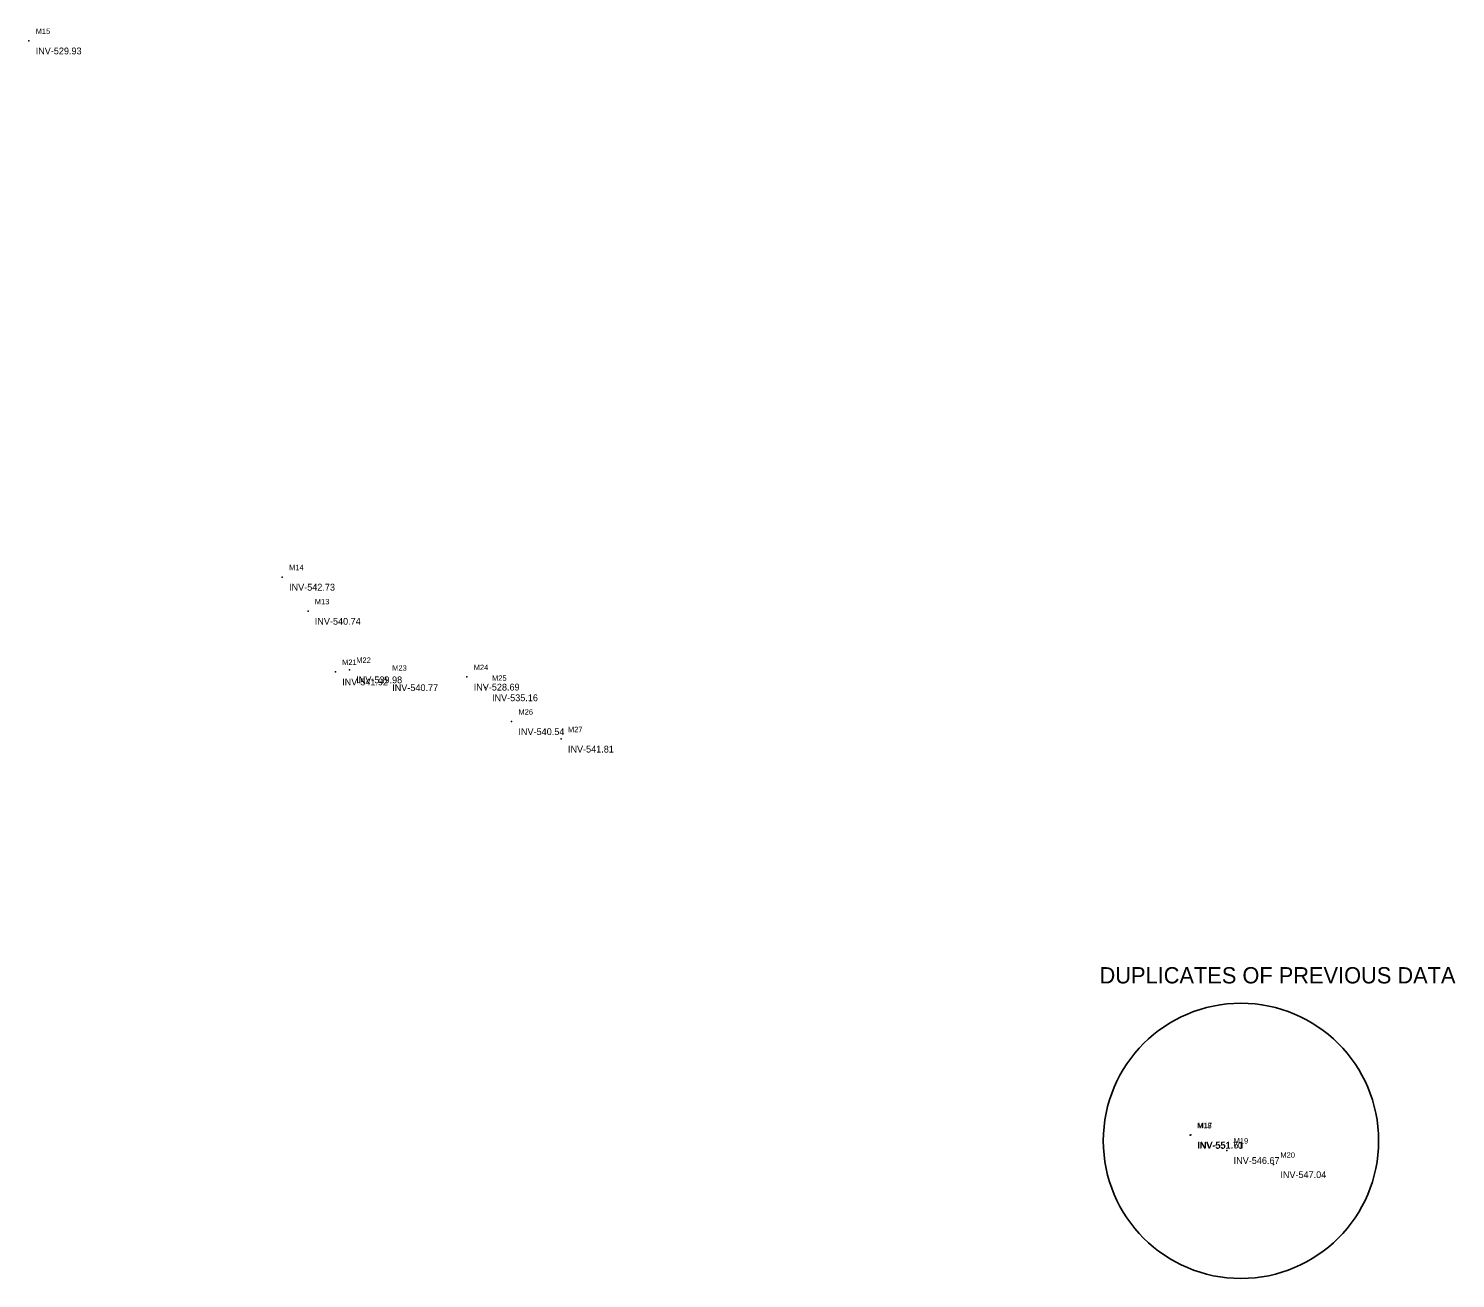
# Model space of a CAD drawing. Extents: x 1728037 to 1741597, y 649934 to 653706.
# Drawn here: x 1728037 to 1729088, y 652785 to 653706 of the extents above; entities that cross this region are included whole.
import ezdxf

# ---------------------------------------------------------------- set-up
doc = ezdxf.new("R2010")
doc.units = 0
for name, color, linetype in [('SURVEY - CENTERLINE - Preliminary', 7, 'Continuous'), ('SURVEY - DRAINAGE - Storm Sewer - Points - Elevations', 7, 'Continuous'), ('SURVEY - DRAINAGE - Storm Sewer - Points - Locators', 7, 'Continuous'), ('SURVEY - DRAINAGE - Storm Sewer - Points - Numbers', 7, 'Continuous')]:
    doc.layers.add(name, color=color, linetype=linetype)

msp = doc.modelspace()

# ---------------------------------------------------------------- linework, layer by layer
at = {"layer": 'SURVEY - CENTERLINE - Preliminary'}
msp.add_circle((1728930, 652886.74), 101.36, dxfattribs=at)
at = {"layer": 'SURVEY - DRAINAGE - Storm Sewer - Points - Locators'}
for p, q in [((1728037.62, 653696.98), (1728037.12, 653696.98)), ((1728037.37, 653696.73), (1728037.37, 653697.23)), ((1728037.37, 653696.98), (1728037.37, 653696.98)), ((1728037.37, 653696.98), (1728037.37, 653696.98)), ((1728224.23, 653302), (1728223.73, 653302)), ((1728223.98, 653301.75), (1728223.98, 653302.25)), ((1728223.98, 653302), (1728223.98, 653302)), ((1728223.98, 653302), (1728223.98, 653302)), ((1728243.19, 653276.88), (1728242.69, 653276.88)), ((1728242.94, 653276.63), (1728242.94, 653277.13)), ((1728242.94, 653276.88), (1728242.94, 653276.88)), ((1728242.94, 653276.88), (1728242.94, 653276.88)), ((1728263.33, 653232.23), (1728262.83, 653232.23)), ((1728263.08, 653231.98), (1728263.08, 653232.48)), ((1728263.08, 653232.23), (1728263.08, 653232.23)), ((1728263.08, 653232.23), (1728263.08, 653232.23)), ((1728273.69, 653233.76), (1728273.19, 653233.76)), ((1728273.44, 653233.51), (1728273.44, 653234.01)), ((1728273.44, 653233.76), (1728273.44, 653233.76)), ((1728273.44, 653233.76), (1728273.44, 653233.76)), ((1728300.18, 653228.01), (1728299.68, 653228.01)), ((1728299.93, 653227.76), (1728299.93, 653228.26)), ((1728299.93, 653228.01), (1728299.93, 653228.01)), ((1728299.93, 653228.01), (1728299.93, 653228.01)), ((1728360.19, 653228.41), (1728359.69, 653228.41)), ((1728359.94, 653228.16), (1728359.94, 653228.66)), ((1728359.94, 653228.41), (1728359.94, 653228.41)), ((1728359.94, 653228.41), (1728359.94, 653228.41)), ((1728373.69, 653220.55), (1728373.19, 653220.55)), ((1728373.44, 653220.3), (1728373.44, 653220.8)), ((1728373.44, 653220.55), (1728373.44, 653220.55)), ((1728373.44, 653220.55), (1728373.44, 653220.55)), ((1728392.91, 653195.36), (1728392.91, 653195.86)), ((1728393.16, 653195.61), (1728392.66, 653195.61)), ((1728392.91, 653195.61), (1728392.91, 653195.61)), ((1728392.91, 653195.61), (1728392.91, 653195.61)), ((1728429.6, 653182.74), (1728429.1, 653182.74)), ((1728429.35, 653182.49), (1728429.35, 653182.99)), ((1728429.35, 653182.74), (1728429.35, 653182.74)), ((1728429.35, 653182.74), (1728429.35, 653182.74)), ((1728892.65, 652890.61), (1728892.65, 652891.11)), ((1728893.31, 652891.15), (1728892.81, 652891.15)), ((1728893.06, 652890.9), (1728893.06, 652891.4)), ((1728893.06, 652891.15), (1728893.06, 652891.15)), ((1728893.06, 652891.15), (1728893.06, 652891.15)), ((1728892.9, 652890.86), (1728892.4, 652890.86)), ((1728892.65, 652890.86), (1728892.65, 652890.86)), ((1728892.65, 652890.86), (1728892.65, 652890.86)), ((1728919.85, 652879.74), (1728919.35, 652879.74)), ((1728919.6, 652879.49), (1728919.6, 652879.99)), ((1728919.6, 652879.74), (1728919.6, 652879.74)), ((1728919.6, 652879.74), (1728919.6, 652879.74)), ((1728954.25, 652869.34), (1728953.75, 652869.34)), ((1728954, 652869.09), (1728954, 652869.59)), ((1728954, 652869.34), (1728954, 652869.34)), ((1728954, 652869.34), (1728954, 652869.34))]:
    msp.add_line(p, q, dxfattribs=at)

# ---------------------------------------------------------------- texts
at = {"layer": 'SURVEY - CENTERLINE - Preliminary'}
msp.add_text('DUPLICATES OF PREVIOUS DATA', height=12, dxfattribs=at).set_placement((1728825.85, 653002.68))
at = {"layer": 'SURVEY - DRAINAGE - Storm Sewer - Points - Elevations'}
for s, p in [('INV-529.93', (1728042.37, 653686.98)), ('INV-542.73', (1728228.98, 653292)), ('INV-540.74', (1728247.94, 653266.88)), ('INV-539.98', (1728278.44, 653223.76)), ('INV-541.92', (1728268.08, 653222.23)), ('INV-540.77', (1728304.93, 653218.01)), ('INV-528.69', (1728364.94, 653218.41)), ('INV-535.16', (1728378.44, 653210.55)), ('INV-540.54', (1728397.91, 653185.61)), ('INV-541.81', (1728434.35, 653172.74)), ('INV-551.70', (1728897.65, 652880.86)), ('INV-551.61', (1728898.06, 652881.15)), ('INV-546.67', (1728924.6, 652869.74)), ('INV-547.04', (1728959, 652859.34))]:
    msp.add_text(s, height=5, dxfattribs=at).set_placement(p)
at = {"layer": 'SURVEY - DRAINAGE - Storm Sewer - Points - Numbers'}
for s, p in [('M15', (1728042.37, 653701.98)), ('M14', (1728228.98, 653307)), ('M13', (1728247.94, 653281.88)), ('M21', (1728268.08, 653237.23)), ('M22', (1728278.44, 653238.76)), ('M23', (1728304.93, 653233.01)), ('M24', (1728364.94, 653233.41)), ('M25', (1728378.44, 653225.55)), ('M26', (1728397.91, 653200.61)), ('M27', (1728434.35, 653187.74)), ('M18', (1728897.65, 652895.86)), ('M17', (1728898.06, 652896.15)), ('M19', (1728924.6, 652884.74)), ('M20', (1728959, 652874.34))]:
    msp.add_text(s, height=4, dxfattribs=at).set_placement(p)

doc.saveas('drawing.dxf')
